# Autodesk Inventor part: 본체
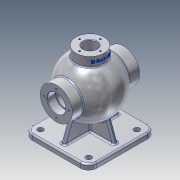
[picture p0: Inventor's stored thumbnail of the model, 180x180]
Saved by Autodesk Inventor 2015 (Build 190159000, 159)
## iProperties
Created: 2025-08
Part Number: 본체
Material: 알루미늄 6061
Document SubType Name: Modeling
Designer: user
Density: 2.7 g/cm^3
Appearance: 알루미늄 - 평지
Author: user
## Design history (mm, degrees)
sketch "스케치2"
  geometry: L1 (-62.5, 65)-(62.5, 65); L2 (62.5, 65)-(62.5, -65); L3 (62.5, -65)-(-62.5, -65); L4 (-62.5, -65)-(-62.5, 65); L5 (-62.5, 65)-(62.5, -65); L6 (62.5, 65)-(-62.5, -65); 1 further point
  constraints: 12 end point, 2 midpoint, 2 parallel, 1 horizontal, 1 perpendicular
  dimensions: "d4" = 125 distance of L2.end L3.end; "d5" = 130 distance of L1.end L2.end
extrude "돌출2" new body sketch "스케치2" distance "d6" = 10; taper "d7" = 0 deg
sketch "스케치4"
  geometry: L1 (62.5, 10)-(62.5, 0) reference; L2 (62.5, 0)-(-62.5, 0) reference; L3 (-62.5, 0)-(-62.5, 10) reference; L4 (-62.5, 10)-(62.5, 10) reference; L5 (0, 139)-(0, 31); L6 (-62.5, 0)-(62.5, 0) reference; A1 r 54 centre (0, 85) between (0, 139) and (0, 31); 3 further points
  constraints: 2 end point, 2 midpoint, 2 point on circle, 1 centre point, 1 coincident, 1 vertical, 1 vertical alignment
  dimensions: "d12" = 108 diameter of A1; "d13" = 85 distance from line of A1.centre L2
revolve "회전1" sketch "스케치4" stored, may be unused: angle "d14" = 90 deg
node "작업 평면1"
sketch "스케치5"
  geometry: C1 r 27 at (0, 0); 1 further point
  constraints: 1 centre point, 1 coincident
  dimensions: "d16" = 54 diameter of C1
extrude "돌출3" join sketch "스케치5" stored distance "d17" = 10; taper "d18" = 0 deg
sketch "스케치6"
  geometry: L1 (-50.5, 4)-(50.5, 4); L2 (50.5, 4)-(50.5, -4); L3 (50.5, -4)-(-50.5, -4); L4 (-50.5, -4)-(-50.5, 4); L5 (-50.5, 4)-(50.5, -4); L6 (50.5, 4)-(-50.5, -4); L7 (-4, -53)-(4, -53); L8 (4, -53)-(4, 53); L9 (4, 53)-(-4, 53); L10 (-4, 53)-(-4, -53); L11 (-4, -53)-(4, 53); L12 (4, -53)-(-4, 53); L13 (-62.5, 65)-(62.5, 65) reference; L14 (62.5, 65)-(62.5, -65) reference; 1 further point
  constraints: 24 end point, 4 midpoint, 4 parallel, 2 horizontal, 2 perpendicular
  dimensions: "d20" = 8 distance of L1.end L2.end; "d21" = 8 distance of L9.end L8.end; "d107" = 12 distance between parallel lines of L9 L13; "d108" = 12 distance between parallel lines of L2 L14
extrude "돌출4" join sketch "스케치6" distance "d23" = 85; taper "d24" = 0 deg
feature "면 기울기1" dims angle "d25" = 20 deg
node "작업 평면2"
sketch "스케치7"
  geometry: L1 (-62.5, 0)-(62.5, 0) reference; C1 r 31 at (0, 85); 3 further points
  constraints: 2 midpoint, 2 vertical alignment, 1 centre point
  dimensions: "d27" = 62 diameter of C1; "d28" = 85 distance of point (0, 0) C1.centre
extrude "돌출5" join sketch "스케치7" distance "d29" = 60; taper "d30" = 0 deg
hole "구멍1" diameter "d33" = 30; stored, may be unused: countersink angle "d37" = 90 deg, drill point angle "d39" = 0 deg; dims "d34" = 6, "d35" = 35, "d36" = 16, "d38" = 20, "d69" = 10, "d70" = 10
fillet "모깎기1" dims "d42" = 16
hole "구멍2" diameter "d45" = 11; stored, may be unused: countersink angle "d49" = 90 deg, drill point angle "d51" = 0 deg; dims "d43" = 16, "d44" = 16, "d46" = 6, "d47" = 35, "d48" = 16, "d50" = 20
hole "구멍3" diameter "d60" = 26; stored, may be unused: countersink angle "d64" = 90 deg, drill point angle "d66" = 0 deg; dims "d58" = 10, "d59" = 10, "d61" = 6, "d62" = 35, "d63" = 16, "d65" = 100
sketch "스케치11"
  geometry: L1 (-27, 131.765)-(-27, 150) reference; L2 (-27, 150)-(-13, 150) reference; L3 (-13, 150)-(-13, 92.483) reference; L4 (-13, 50)-(13, 50) reference; L5 (13, 50)-(13, 77.517) reference; L6 (13, 150)-(27, 150) reference; L7 (27, 150)-(27, 131.765) reference; L8 (37.385, 46.034)-(50.5, 10) reference; L9 (50.5, 10)-(62.5, 10) reference; L10 (62.5, 10)-(62.5, 0) reference; L11 (62.5, 0)-(-62.5, 0) reference; L12 (-62.5, 0)-(-62.5, 10) reference; L13 (-62.5, 10)-(-50.5, 10) reference; L14 (-50.5, 10)-(-37.385, 46.034) reference; L15 (0, 129)-(0, 41); L16 (4, 10)-(4, 48.031) reference; L17 (-13, 77.517)-(-13, 50) reference; L18 (13, 92.483)-(13, 150) reference; C1 r 17.5 at (0, 85) reference; A1 r 54 centre (0, 85) between (37.385, 46.034) and (27, 131.765) reference; A2 r 54 centre (0, 85) between (-27, 131.765) and (-37.385, 46.034) reference; A3 r 44 centre (0, 85) between (0, 129) and (4, 41.182); A4 r 15 centre (0, 85) between (-13, 92.483) and (-13, 77.517) reference; A5 r 15 centre (0, 85) between (13, 77.517) and (13, 92.483) reference; 2 further points
  constraints: 3 point on circle, 2 coincident, 2 end point, 1 centre point, 1 midpoint, 1 parallel, 1 point on line
  dimensions: "d67" = 88 diameter of A3
revolve "회전2" sketch "스케치11" stored, may be unused: angle "d68" = 90 deg
sketch "스케치14"
  geometry: C1 r 3.442 at (0, 20); 1 further point
  constraints: 1 centre point, 1 vertical alignment
  dimensions: "d71" = 20 distance of point (0, 0) C1.centre
hole "구멍4" sketch "스케치14" at (0, 20) diameter "d72" = 3.242; stored, may be unused: countersink angle "d76" = 90 deg, drill point angle "d78" = 118 deg; dims "d73" = 12, "d74" = 35, "d75" = 16, "d77" = 15
sketch "스케치15"
  geometry: L1 (-46.5, -75)-(46.5, -75) reference; L2 (46.5, -85)-(46.5, -75) reference; L3 (46.5, -85)-(-46.5, -85) reference; L4 (-46.5, -85)-(-46.5, -75) reference; C1 r 3.321 at (0, 24); C2 r 17.5 at (0, 0) reference; C3 r 31 at (0, 0) reference; 1 further point
  constraints: 1 centre point, 1 vertical alignment
  dimensions: "d82" = 24 distance of C2.centre C1.centre
hole "구멍5" sketch "스케치15" at (0, 24) diameter "d83" = 3.242; stored, may be unused: countersink angle "d87" = 90 deg, drill point angle "d89" = 118 deg; dims "d84" = 12, "d85" = 35, "d86" = 16, "d88" = 15
chamfer "모따기1" distance "d94" = 1; stored, may be unused: second distance "d95" = 2, angle "d96" = 45 deg
fillet "모깎기3" dims "d97" = 0.6
fillet "모깎기4" dims "d98" = 3
fillet "모깎기5" dims "d99" = 3
fillet "모깎기6" dims "d100" = 3
fillet "모깎기7" dims "d101" = 3
fillet "모깎기8" dims "d102" = 3
sketch "스케치16"
  geometry: L1 (14, 150)-(-14, 150) reference; 2 further points
  constraints: 1 vertical alignment, 1 other
  dimensions: "d103" = 9 distance from line of point (0, 141) L1
feature "엠보싱1" sketch "스케치16" dims "d17" = 10, "d104" = 1, "d105" = 0
fillet "모깎기9" dims "d106" = 3
node "솔리드2"
mirror "대칭1"
mirror "대칭2"
pattern_linear "직사각형 패턴1" dims "d54" = 93, "d57" = 93
pattern_circular "원형 패턴1" dims angle "d80" = 360 deg
pattern_circular "원형 패턴2" dims angle "d91" = 360 deg
mirror "대칭3"
node "작업 평면3"
node "절단 모서리 투영1"
node "절단 모서리 투영2"
node "절단 모서리 투영3"
other parameters: "d26" = -65
